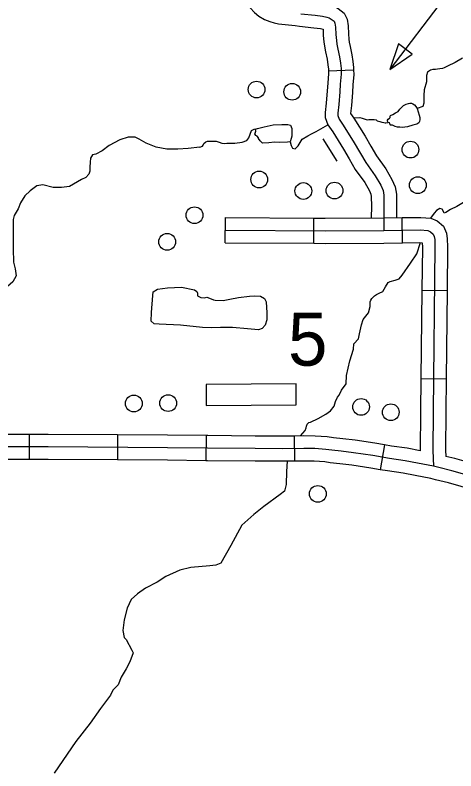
# Model space of a CAD drawing. Extents: x 1382482 to 1385815, y 1168351 to 1170484.
# Drawn here: x 1383658.5 to 1383763.7, y 1168998.2 to 1169178.5 of the extents above; entities that cross this region are included whole.
import ezdxf

# ---------------------------------------------------------------- set-up
doc = ezdxf.new("R2010")
doc.units = 0
for name, color, linetype in [('32', 7, 'Continuous'), ('35', 7, 'Continuous'), ('45', 7, 'Continuous'), ('57', 7, 'Continuous'), ('Default', 7, 'Continuous')]:
    doc.layers.add(name, color=color, linetype=linetype)

msp = doc.modelspace()

# ---------------------------------------------------------------- linework, layer by layer
at = {"layer": '32'}
for p, q in [((1383708.66, 1169124.15), (1383708.69, 1169130.15)), ((1383729.78, 1169124.03), (1383729.81, 1169130.03)), ((1383750.95, 1169124.14), (1383750.88, 1169130.14)), ((1383755.59, 1169112.85), (1383761.59, 1169112.79)), ((1383755.37, 1169091.73), (1383761.37, 1169091.67)), ((1383661.8, 1169078.44), (1383661.79, 1169072.44)), ((1383682.93, 1169078.33), (1383682.9, 1169072.33)), ((1383704.07, 1169078.16), (1383704, 1169072.16)), ((1383725.12, 1169078.04), (1383725.18, 1169072.04)), ((1383746.65, 1169075.92), (1383745.62, 1169070.01))]:
    msp.add_line(p, q, dxfattribs=at)
for points in [[(1383708.69, 1169130.15), (1383729.81, 1169130.03)], [(1383729.81, 1169130.03), (1383732.53, 1169130.01), (1383746.47, 1169130.09), (1383750.88, 1169130.14)], [(1383750.88, 1169130.14), (1383755.3, 1169130.2), (1383757.72, 1169130.01), (1383759.25, 1169129.36), (1383760.74, 1169128.08), (1383761.48, 1169126.46), (1383761.65, 1169125.12), (1383761.7, 1169123.17), (1383761.59, 1169112.79)], [(1383708.67, 1169127.15), (1383732.53, 1169127.01), (1383746.49, 1169127.09), (1383755.2, 1169127.2), (1383757, 1169127.06), (1383757.64, 1169126.78), (1383758.29, 1169126.23), (1383758.56, 1169125.63), (1383758.66, 1169124.89), (1383758.7, 1169123.14), (1383758.29, 1169083.9), (1383758.19, 1169074.59), (1383758.38, 1169070.86)], [(1383708.66, 1169124.15), (1383729.78, 1169124.03)], [(1383729.78, 1169124.03), (1383732.53, 1169124.01), (1383746.52, 1169124.09), (1383750.95, 1169124.14)], [(1383750.95, 1169124.14), (1383755.1, 1169124.19), (1383755.67, 1169124.15), (1383755.7, 1169123.12), (1383755.59, 1169112.85)], [(1383755.59, 1169112.85), (1383755.37, 1169091.73)], [(1383761.59, 1169112.79), (1383761.37, 1169091.67)], [(1383755.37, 1169091.73), (1383755.29, 1169083.93), (1383755.19, 1169074.5)], [(1383761.37, 1169091.67), (1383761.29, 1169083.87), (1383761.2, 1169074.65), (1383761.27, 1169073.19)], [(1383661.8, 1169078.44), (1383654.34, 1169078.44)], [(1383682.93, 1169078.33), (1383666.38, 1169078.44), (1383661.8, 1169078.44)], [(1383704.07, 1169078.16), (1383694.88, 1169078.26), (1383682.93, 1169078.33)], [(1383725.12, 1169078.04), (1383722.42, 1169078.01), (1383715.8, 1169078.04), (1383704.47, 1169078.15), (1383704.07, 1169078.16)], [(1383746.65, 1169075.92), (1383744.36, 1169076.33), (1383739.69, 1169077.04), (1383736.68, 1169077.38), (1383734.45, 1169077.64), (1383732.98, 1169077.83), (1383730.15, 1169078.04), (1383727.43, 1169078.06), (1383725.12, 1169078.04)], [(1383755.19, 1169074.5), (1383752.08, 1169075.12), (1383748.33, 1169075.63), (1383746.65, 1169075.92)], [(1383765.87, 1169068.88), (1383762.73, 1169069.75), (1383759.64, 1169070.5), (1383758.38, 1169070.86), (1383754.56, 1169071.56), (1383751.58, 1169072.16), (1383747.87, 1169072.67), (1383743.88, 1169073.37), (1383739.29, 1169074.06), (1383736.34, 1169074.4), (1383734.08, 1169074.66), (1383732.68, 1169074.84), (1383730.03, 1169075.04), (1383727.43, 1169075.06), (1383722.43, 1169075.01), (1383715.77, 1169075.04), (1383704.44, 1169075.15), (1383694.85, 1169075.26), (1383666.37, 1169075.44), (1383651.31, 1169075.45)], [(1383661.79, 1169072.44), (1383651.28, 1169072.45), (1383640.63, 1169072.61)], [(1383682.9, 1169072.33), (1383666.36, 1169072.44), (1383661.79, 1169072.44)], [(1383704, 1169072.16), (1383694.82, 1169072.26), (1383682.9, 1169072.33)], [(1383725.18, 1169072.04), (1383722.44, 1169072.01), (1383715.75, 1169072.04), (1383704.41, 1169072.15), (1383704, 1169072.16)], [(1383745.62, 1169070.01), (1383743.39, 1169070.4), (1383738.89, 1169071.09), (1383735.99, 1169071.42), (1383733.72, 1169071.68), (1383732.38, 1169071.86), (1383729.9, 1169072.04), (1383727.44, 1169072.06), (1383725.18, 1169072.04)], [(1383767.77, 1169071.39), (1383766.78, 1169071.74), (1383763.48, 1169072.65), (1383761.27, 1169073.19)], [(1383765.74, 1169065.74), (1383764.97, 1169066.02), (1383761.97, 1169066.85), (1383758.87, 1169067.6), (1383757.69, 1169067.94), (1383754, 1169068.62), (1383751.09, 1169069.2), (1383747.4, 1169069.7), (1383745.62, 1169070.01)]]:
    msp.add_lwpolyline(points, dxfattribs=at)
at = {"layer": '35'}
for points in [[(1383765.32, 1169168.17), (1383763.54, 1169167.12), (1383761.67, 1169166.24), (1383760.94, 1169165.86), (1383760.51, 1169165.73), (1383759.86, 1169165.63), (1383759.28, 1169165.56), (1383758.85, 1169165.51), (1383758.18, 1169165.46), (1383757.65, 1169165.31), (1383756.94, 1169164.81), (1383756.69, 1169164.07), (1383756.72, 1169162.53), (1383756.1, 1169160.63), (1383756.02, 1169159.27), (1383756.07, 1169158.26), (1383756.07, 1169157.45), (1383755.82, 1169156.64), (1383754.43, 1169156.19)], [(1383747.55, 1169152.87), (1383747.48, 1169153.01), (1383747.42, 1169153.17), (1383747.42, 1169153.4), (1383747.56, 1169153.67), (1383747.85, 1169153.91), (1383748.04, 1169154.05), (1383748.05, 1169154.2), (1383748.01, 1169154.29), (1383748.01, 1169154.37), (1383748.12, 1169154.54), (1383748.62, 1169154.71), (1383749.32, 1169155.11), (1383749.9, 1169155.48), (1383750.36, 1169156.05), (1383750.81, 1169156.52), (1383751.22, 1169156.92), (1383751.81, 1169157.18), (1383752.43, 1169157.38), (1383752.74, 1169157.43), (1383753.1, 1169157.43), (1383753.46, 1169157.31), (1383753.84, 1169157.06), (1383754.13, 1169156.65), (1383754.43, 1169156.19), (1383754.71, 1169155.38)], [(1383754.71, 1169155.38), (1383754.96, 1169154.61), (1383755.14, 1169154.01), (1383755.14, 1169153.55), (1383755.01, 1169153.1), (1383754.84, 1169152.75), (1383754.42, 1169152.47), (1383753.41, 1169152.2), (1383752.15, 1169151.82), (1383751.53, 1169151.69), (1383750.93, 1169151.65), (1383750.33, 1169151.74), (1383749.74, 1169151.76), (1383749.22, 1169151.89), (1383748.92, 1169152.05), (1383748.59, 1169152.18), (1383748.35, 1169152.18), (1383748.11, 1169152.22), (1383748.04, 1169152.32), (1383747.97, 1169152.49), (1383747.94, 1169152.62), (1383747.83, 1169152.75), (1383747.55, 1169152.87)], [(1383739.27, 1169153.99), (1383740.81, 1169154.03), (1383741.34, 1169153.9), (1383741.8, 1169153.7), (1383742.28, 1169153.55), (1383742.53, 1169153.47), (1383742.91, 1169153.52), (1383743.39, 1169153.52), (1383744.22, 1169153.52), (1383744.65, 1169153.45), (1383744.95, 1169153.27), (1383745.58, 1169153.04), (1383746.04, 1169152.94), (1383746.54, 1169152.81), (1383746.82, 1169152.74), (1383747.02, 1169152.74), (1383747.55, 1169152.87)], [(1383781.03, 1169153.45), (1383781.59, 1169152.21), (1383782.15, 1169150.22), (1383781.62, 1169147.62), (1383781.06, 1169146.89), (1383778.94, 1169145.92), (1383777.98, 1169145.21), (1383775.83, 1169140.96), (1383773.97, 1169138.98), (1383772.58, 1169138.05), (1383769.39, 1169136.58), (1383767.33, 1169134.88), (1383763.91, 1169132.81), (1383762.42, 1169132.11), (1383761.34, 1169131.37), (1383760.88, 1169131.19), (1383760.79, 1169131.6), (1383760.47, 1169132.2), (1383759.87, 1169132.34), (1383759.09, 1169131.88), (1383758.53, 1169131.19), (1383757.63, 1169130.02)], [(1383720.42, 1169148.14), (1383719.01, 1169147.99), (1383717.54, 1169147.94), (1383717.19, 1169148.24), (1383716.99, 1169148.5), (1383716.59, 1169149), (1383716.59, 1169149.15), (1383716.28, 1169149.56), (1383715.93, 1169149.76), (1383715.73, 1169150.11), (1383715.78, 1169150.31), (1383715.93, 1169150.77), (1383715.88, 1169151.27), (1383716.33, 1169151.37), (1383716.99, 1169151.58), (1383717.95, 1169151.83)], [(1383717.95, 1169151.83), (1383720.07, 1169152.28), (1383722.14, 1169152.38), (1383723.55, 1169152.33), (1383724.26, 1169152.23), (1383724.51, 1169151.37), (1383724.51, 1169150.47), (1383724.56, 1169149.96), (1383724.56, 1169149.56), (1383724.41, 1169149), (1383724.16, 1169148.19), (1383723.5, 1169148.14), (1383721.53, 1169148.09), (1383720.42, 1169148.14)], [(1383724.16, 1169148.19), (1383724.41, 1169147.39), (1383724.71, 1169146.73), (1383725.37, 1169146.58), (1383726.02, 1169147.28), (1383727.03, 1169148.85), (1383728.35, 1169149.66), (1383729.26, 1169150.16), (1383730.37, 1169150.67), (1383733.12, 1169152.25)], [(1383702.61, 1169146.92), (1383703.24, 1169147.16), (1383703.39, 1169147.41), (1383703.49, 1169147.79), (1383703.97, 1169148.19), (1383704.37, 1169148.37), (1383704.72, 1169148.42), (1383705.68, 1169148.42), (1383706.47, 1169148.42), (1383707.22, 1169148.12), (1383707.83, 1169147.94), (1383708.51, 1169147.86), (1383709.01, 1169147.92), (1383710.96, 1169147.94), (1383712.72, 1169148.12), (1383713.78, 1169148.52), (1383714.29, 1169149.15), (1383714.92, 1169150.92), (1383715.68, 1169151.32), (1383715.88, 1169151.27)], [(1383702.61, 1169146.92), (1383699.78, 1169146.62), (1383697.31, 1169146.47), (1383694.73, 1169146.47), (1383692.16, 1169146.92), (1383689.79, 1169147.93), (1383688.12, 1169148.84), (1383687.16, 1169149.3), (1383686.4, 1169149.35), (1383685.5, 1169149.3), (1383683.48, 1169148.69), (1383680.95, 1169147.38), (1383679.29, 1169146.11), (1383677.77, 1169145.31), (1383676.97, 1169145.15), (1383676.46, 1169144.3), (1383676.41, 1169143.39), (1383676.31, 1169142.18), (1383676.31, 1169141.22), (1383676.11, 1169140.51), (1383675.35, 1169139.7), (1383674.34, 1169139.25), (1383671.44, 1169137.58), (1383669.52, 1169137.33), (1383667.55, 1169137.33), (1383665.06, 1169137.98), (1383663.65, 1169137.76), (1383662.99, 1169137.25)], [(1383662.99, 1169137.25), (1383662.04, 1169136.55), (1383660.78, 1169135.34), (1383659.77, 1169133.67), (1383659.21, 1169132.26), (1383658.25, 1169130.67), (1383658, 1169129.66), (1383658, 1169122.69), (1383658.07, 1169119.5), (1383658.5, 1169117.89), (1383658.76, 1169116.23), (1383657.95, 1169114.81), (1383654.74, 1169112.16)], [(1383726.61, 1169078.07), (1383727.72, 1169079.37), (1383728, 1169079.97), (1383728.05, 1169080.43), (1383728.23, 1169080.89), (1383728.6, 1169081.26), (1383729.01, 1169081.31), (1383730.81, 1169082.23), (1383732.65, 1169083.24), (1383733.76, 1169084.07), (1383734.63, 1169085.13), (1383734.98, 1169086.25), (1383735.46, 1169087.3), (1383735.83, 1169087.8), (1383736.41, 1169089.01), (1383737.49, 1169090.5), (1383737.58, 1169092.49), (1383738.36, 1169095.99), (1383739.24, 1169098.79), (1383739.31, 1169100.06), (1383740.46, 1169101.26), (1383740.69, 1169102.41), (1383741.15, 1169104.53), (1383741.61, 1169105.82), (1383742.87, 1169107.4), (1383743.24, 1169108.94), (1383743.24, 1169110.09), (1383743.39, 1169110.43), (1383743.64, 1169110.84), (1383744.3, 1169111.52), (1383744.76, 1169111.8), (1383745.41, 1169112.12), (1383746.29, 1169112.55), (1383746.91, 1169113.61), (1383747.51, 1169114.65), (1383748, 1169114.94), (1383749.24, 1169115.21), (1383750.18, 1169115.58), (1383750.91, 1169116.41), (1383752.85, 1169119.31), (1383754.37, 1169121.47), (1383755.28, 1169124.2)], [(1383703.25, 1169103.91), (1383697.96, 1169104.47), (1383692.89, 1169104.74), (1383691.69, 1169104.79), (1383690.96, 1169105.48), (1383691.05, 1169107.55), (1383691.33, 1169111.56), (1383691.46, 1169112.44), (1383692.43, 1169113.08), (1383694.83, 1169113.36), (1383698.19, 1169113.54), (1383701.27, 1169112.9), (1383701.82, 1169112.53), (1383702.01, 1169112.11), (1383702.05, 1169111.52), (1383702.79, 1169111.05), (1383703.67, 1169111.01), (1383704.27, 1169111.15), (1383704.86, 1169110.96), (1383705.83, 1169110.55), (1383706.25, 1169110.46)], [(1383706.25, 1169110.46), (1383708.13, 1169110.41), (1383709.75, 1169110.69), (1383711.82, 1169111.05), (1383714.4, 1169111.42), (1383715.59, 1169111.52), (1383717.02, 1169111.38), (1383717.99, 1169110.82), (1383718.4, 1169110.04), (1383718.59, 1169107.46), (1383718.54, 1169105.76), (1383718.17, 1169104.51), (1383717.44, 1169103.68), (1383716.56, 1169103.41), (1383713.94, 1169103.59), (1383710.39, 1169103.96), (1383707.53, 1169103.91), (1383705.37, 1169103.82), (1383703.25, 1169103.91)], [(1383723.4, 1169072.01), (1383723.29, 1169069.56), (1383723.2, 1169066.45), (1383722.77, 1169064.85), (1383721.75, 1169064.1), (1383717.89, 1169061.25), (1383715.47, 1169059.31), (1383712.63, 1169056.74), (1383709.95, 1169051.92), (1383707.62, 1169047.73), (1383706.43, 1169047.2), (1383704.98, 1169047.09), (1383700.39, 1169046.71), (1383697.8, 1169046.04), (1383694.49, 1169044.54), (1383692.37, 1169043.2), (1383689.61, 1169041.77), (1383687.71, 1169040.39), (1383686.15, 1169039.01), (1383685.2, 1169036.94), (1383684.51, 1169034.18), (1383684.21, 1169031.67), (1383684.47, 1169029.99), (1383685, 1169029.49), (1383686.32, 1169026.96), (1383686.63, 1169026.36), (1383685.89, 1169024.2), (1383684.97, 1169022.47), (1383683.83, 1169020.54), (1383683.06, 1169018.71), (1383681.83, 1169017.43), (1383681.28, 1169016.19), (1383678.88, 1169013.02), (1383676.4, 1169009.57), (1383672.95, 1169005.17), (1383667.83, 1168997.58)]]:
    msp.add_lwpolyline(points, dxfattribs=at)
at = {"layer": '45'}
msp.add_line((1383733.3, 1169165.17), (1383739.29, 1169165.37), dxfattribs=at)
for points in [[(1383707.32, 1169189.07), (1383713.01, 1169181.96), (1383714.6, 1169180.18), (1383715.65, 1169179.05), (1383716.69, 1169178.22), (1383717.98, 1169177.43), (1383719.29, 1169176.95), (1383720.34, 1169176.64), (1383721.38, 1169176.41), (1383725.37, 1169175.94)], [(1383726.08, 1169181.89), (1383727.04, 1169181.78), (1383730.47, 1169181.39), (1383732.41, 1169181.16), (1383733.7, 1169180.86), (1383734.61, 1169180.56), (1383735.63, 1169180.03), (1383737.01, 1169178.89), (1383737.72, 1169177.47), (1383738, 1169175.93), (1383738.04, 1169174.02), (1383738.18, 1169172.7), (1383738.26, 1169171.98), (1383738.48, 1169170.93), (1383738.89, 1169168.99), (1383739.12, 1169167.37), (1383739.27, 1169165.97), (1383739.29, 1169165.37)], [(1383726.69, 1169178.8), (1383730.12, 1169178.41), (1383731.89, 1169178.2), (1383732.88, 1169177.97), (1383733.44, 1169177.79), (1383733.97, 1169177.51), (1383734.61, 1169176.98), (1383734.84, 1169176.52), (1383735, 1169175.62), (1383735.05, 1169173.82), (1383735.2, 1169172.39), (1383735.29, 1169171.51), (1383735.54, 1169170.31), (1383735.93, 1169168.47), (1383736.14, 1169167), (1383736.28, 1169165.75), (1383736.33, 1169164.39), (1383736.1, 1169162.02), (1383735.99, 1169160.17), (1383735.76, 1169157.17), (1383735.53, 1169155.05), (1383735.53, 1169154.5), (1383735.81, 1169153.67), (1383736.82, 1169152.24), (1383739.45, 1169148.01), (1383742.21, 1169143.26), (1383744.47, 1169140.13), (1383745.76, 1169137.87), (1383746.31, 1169136.63), (1383746.49, 1169135.48), (1383746.54, 1169132.85), (1383746.49, 1169127.09)], [(1383725.37, 1169175.94), (1383726.34, 1169175.82), (1383729.78, 1169175.43), (1383731.38, 1169175.24), (1383732.01, 1169175.09), (1383732.05, 1169173.63), (1383732.21, 1169172.07), (1383732.32, 1169171.04), (1383732.61, 1169169.69), (1383732.98, 1169167.95), (1383733.17, 1169166.62), (1383733.29, 1169165.54), (1383733.3, 1169165.17)], [(1383733.3, 1169165.17), (1383733.32, 1169164.49), (1383733.1, 1169162.25), (1383733, 1169160.37), (1383732.77, 1169157.45), (1383732.53, 1169155.22), (1383732.53, 1169154.01), (1383733.1, 1169152.3), (1383734.32, 1169150.58), (1383736.87, 1169146.46), (1383738.21, 1169144.16)], [(1383739.29, 1169165.37), (1383739.33, 1169164.3), (1383739.09, 1169161.79), (1383738.99, 1169159.97), (1383738.75, 1169156.9), (1383738.54, 1169155), (1383739.32, 1169153.9), (1383742.02, 1169149.55), (1383743.4, 1169147.18)], [(1383743.4, 1169147.18), (1383744.73, 1169144.9), (1383746.99, 1169141.75), (1383748.44, 1169139.23), (1383749.21, 1169137.49), (1383749.49, 1169135.74), (1383749.54, 1169132.86), (1383749.52, 1169130.13)], [(1383738.21, 1169144.16), (1383739.69, 1169141.63), (1383741.94, 1169138.5), (1383743.08, 1169136.51), (1383743.41, 1169135.77), (1383743.5, 1169135.21), (1383743.54, 1169132.84), (1383743.52, 1169130.07)]]:
    msp.add_lwpolyline(points, dxfattribs=at)
at = {"layer": '57'}
for p, q in [((1383725.55, 1169090.5), (1383704.05, 1169090.33)), ((1383704.05, 1169090.33), (1383704.09, 1169085.33)), ((1383725.59, 1169085.5), (1383725.55, 1169090.5)), ((1383704.09, 1169085.33), (1383725.59, 1169085.5))]:
    msp.add_line(p, q, dxfattribs=at)
at = {"layer": 'Default'}
for points in [[(1383752.42, 1169195.99), (1383760.91, 1169182.59), (1383747.93, 1169165.46)], [(1383731.93, 1169148.91), (1383735.29, 1169143.59)]]:
    msp.add_lwpolyline(points, dxfattribs=at)
msp.add_lwpolyline([(1383753.25, 1169169.1), (1383750, 1169171.57), (1383747.93, 1169165.46)], close=True, dxfattribs=at)
for centre in [(1383716.13, 1169160.69), (1383724.63, 1169160.17), (1383752.86, 1169146.37), (1383716.75, 1169139.25), (1383754.63, 1169137.88), (1383727.29, 1169136.5), (1383734.73, 1169136.59), (1383701.31, 1169130.71), (1383694.78, 1169124.36), (1383686.81, 1169085.81), (1383695.02, 1169085.9), (1383741.07, 1169084.98), (1383748.16, 1169083.71), (1383730.75, 1169064.24)]:
    msp.add_circle(centre, 2, dxfattribs=at)

# ---------------------------------------------------------------- texts
at = {"layer": '57'}
msp.add_text('5', height=12.67, dxfattribs=at).set_placement((1383723.62, 1169094.83))

doc.saveas('drawing.dxf')
